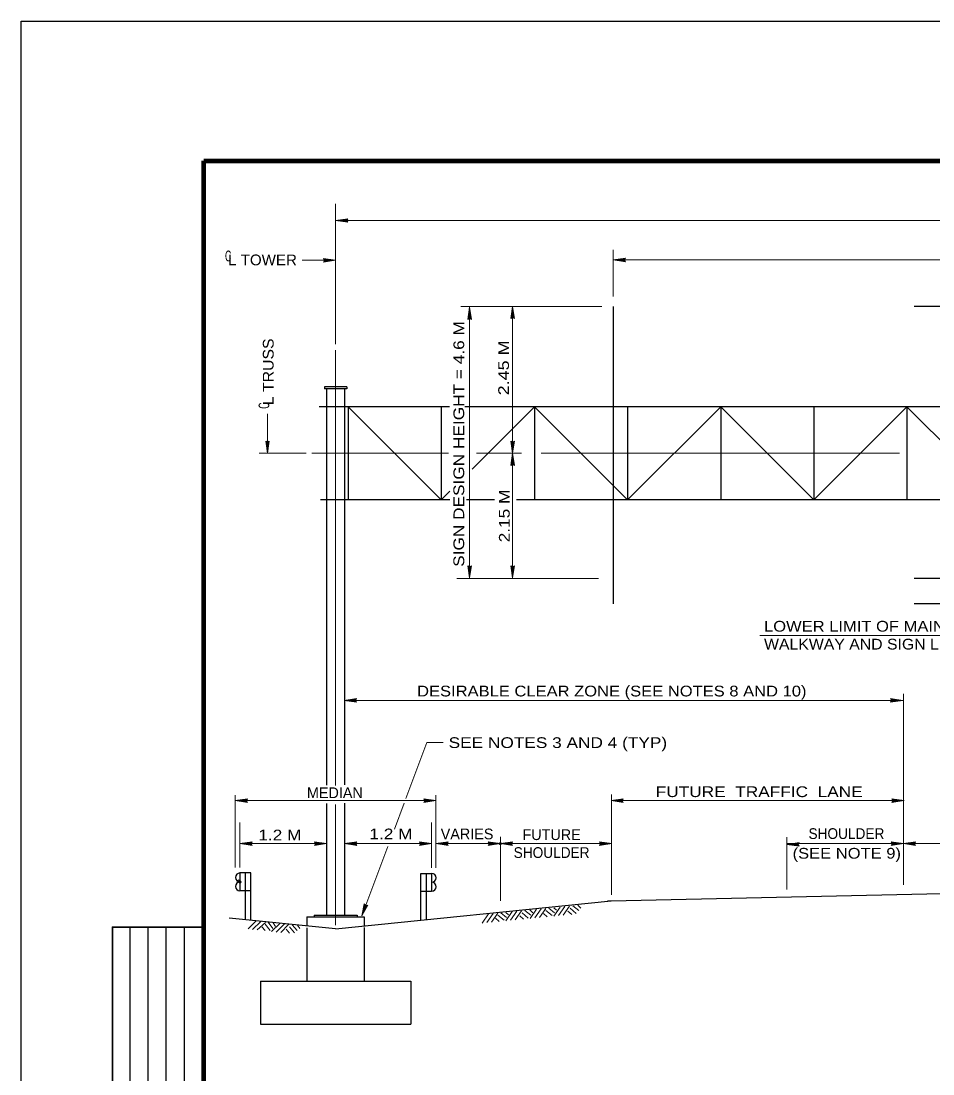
# Model space of a CAD drawing. Extents: x 312601.858 to 312602.699, y 144420.127 to 144420.721.
# Drawn here: x 312601.8578 to 312602.1123, y 144420.4268 to 144420.7208 of the extents above; entities that cross this region are included whole.
import ezdxf
from ezdxf.enums import TextEntityAlignment as Align

# ---------------------------------------------------------------- set-up
doc = ezdxf.new("R2010")
doc.units = 0
doc.header["$LTSCALE"] = 0.0012
doc.header["$PDMODE"] = 32
doc.header["$PDSIZE"] = 0.0006
doc.linetypes.add('DOT_DASHED', pattern=[7.7, 5, -1.2, 0.3, -1.2])
doc.linetypes.add('LONG_DASHED', pattern=[7.5, 6, -1.5])
for name, color, linetype, lineweight in [('1', 7, 'Continuous', 13), ('2', 7, 'Continuous', 13), ('39', 7, 'Continuous', 13), ('60', 7, 'Continuous', 25)]:
    doc.layers.add(name, color=color, linetype=linetype, lineweight=lineweight)

msp = doc.modelspace()

# ---------------------------------------------------------------- hatches: boundary and pattern name
at = {"layer": '39'}
for points in [[(312601.9487, 144420.6651), (312601.949, 144420.6646), (312601.9456, 144420.6651), (312601.949, 144420.6656)], [(312601.9425, 144420.654), (312601.9422, 144420.6545), (312601.9456, 144420.654), (312601.9422, 144420.6535)], [(312601.9425, 144420.654), (312601.9422, 144420.6545), (312601.9456, 144420.654), (312601.9422, 144420.6535)], [(312602.0262, 144420.6541), (312602.0265, 144420.6536), (312602.0231, 144420.6541), (312602.0265, 144420.6546)], [(312601.983, 144420.6378), (312601.9825, 144420.6375), (312601.983, 144420.6409), (312601.9835, 144420.6375)], [(312601.983, 144420.6378), (312601.9825, 144420.6375), (312601.983, 144420.6409), (312601.9835, 144420.6375)], [(312601.995, 144420.638), (312601.9945, 144420.6377), (312601.995, 144420.6411), (312601.9955, 144420.6377)], [(312601.995, 144420.638), (312601.9945, 144420.6377), (312601.995, 144420.6411), (312601.9955, 144420.6377)], [(312601.9266, 144420.6032), (312601.9271, 144420.6035), (312601.9266, 144420.6001), (312601.9261, 144420.6035)], [(312601.995, 144420.6032), (312601.9955, 144420.6035), (312601.995, 144420.6001), (312601.9945, 144420.6035)], [(312601.995, 144420.6032), (312601.9955, 144420.6035), (312601.995, 144420.6001), (312601.9945, 144420.6035)], [(312601.995, 144420.597), (312601.9945, 144420.5967), (312601.995, 144420.6001), (312601.9955, 144420.5967)], [(312601.995, 144420.597), (312601.9945, 144420.5967), (312601.995, 144420.6001), (312601.9955, 144420.5967)], [(312601.983, 144420.5684), (312601.9835, 144420.5687), (312601.983, 144420.5653), (312601.9825, 144420.5687)], [(312601.983, 144420.5684), (312601.9835, 144420.5687), (312601.983, 144420.5653), (312601.9825, 144420.5687)], [(312601.995, 144420.5684), (312601.9955, 144420.5687), (312601.995, 144420.5653), (312601.9945, 144420.5687)], [(312601.995, 144420.5684), (312601.9955, 144420.5687), (312601.995, 144420.5653), (312601.9945, 144420.5687)], [(312601.9511, 144420.5311), (312601.9514, 144420.5306), (312601.948, 144420.5311), (312601.9514, 144420.5316)], [(312602.1008, 144420.5311), (312602.1005, 144420.5316), (312602.1039, 144420.5311), (312602.1005, 144420.5306)], [(312602.1008, 144420.5311), (312602.1005, 144420.5316), (312602.1039, 144420.5311), (312602.1005, 144420.5306)], [(312601.9207, 144420.5031), (312601.921, 144420.5026), (312601.9176, 144420.5031), (312601.921, 144420.5036)], [(312601.9705, 144420.5031), (312601.9702, 144420.5036), (312601.9736, 144420.5031), (312601.9702, 144420.5026)], [(312602.0256, 144420.5031), (312602.0259, 144420.5026), (312602.0225, 144420.5031), (312602.0259, 144420.5036)], [(312602.1012, 144420.5031), (312602.1009, 144420.5036), (312602.1043, 144420.5031), (312602.1009, 144420.5026)], [(312601.922, 144420.4911), (312601.9223, 144420.4906), (312601.9189, 144420.4911), (312601.9223, 144420.4916)], [(312601.94, 144420.4911), (312601.9397, 144420.4916), (312601.9431, 144420.4911), (312601.9397, 144420.4906)], [(312601.94, 144420.4911), (312601.9397, 144420.4916), (312601.9431, 144420.4911), (312601.9397, 144420.4906)], [(312601.9512, 144420.4911), (312601.9515, 144420.4906), (312601.9481, 144420.4911), (312601.9515, 144420.4916)], [(312601.9693, 144420.4911), (312601.969, 144420.4916), (312601.9724, 144420.4911), (312601.969, 144420.4906)], [(312601.9767, 144420.4911), (312601.977, 144420.4906), (312601.9736, 144420.4911), (312601.977, 144420.4916)], [(312601.9885, 144420.4911), (312601.9882, 144420.4916), (312601.9916, 144420.4911), (312601.9882, 144420.4906)], [(312601.9947, 144420.4911), (312601.995, 144420.4906), (312601.9916, 144420.4911), (312601.995, 144420.4916)], [(312602.0196, 144420.4911), (312602.0193, 144420.4916), (312602.0227, 144420.4911), (312602.0193, 144420.4906)], [(312602.101, 144420.4911), (312602.1007, 144420.4916), (312602.1041, 144420.4911), (312602.1007, 144420.4906)], [(312602.101, 144420.4911), (312602.1007, 144420.4916), (312602.1041, 144420.4911), (312602.1007, 144420.4906)], [(312602.1072, 144420.4911), (312602.1075, 144420.4906), (312602.1041, 144420.4911), (312602.1075, 144420.4916)], [(312602.1072, 144420.4911), (312602.1075, 144420.4906), (312602.1041, 144420.4911), (312602.1075, 144420.4916)], [(312602.0747, 144420.4909), (312602.075, 144420.4904), (312602.0716, 144420.4909), (312602.075, 144420.4914)], [(312601.954, 144420.4738), (312601.9546, 144420.4739), (312601.9529, 144420.4709), (312601.9536, 144420.4743)]]:
    msp.add_hatch(color=256, dxfattribs=at).paths.add_polyline_path(points)

# ---------------------------------------------------------------- linework, layer by layer
at = {"layer": '1'}
for p, q in [((312602.0132, 144420.4739), (312602.0141, 144420.4731)), ((312601.9865, 144420.4689), (312601.9883, 144420.4715)), ((312601.9878, 144420.4691), (312601.9896, 144420.4716)), ((312601.9891, 144420.4692), (312601.9909, 144420.4717)), ((312601.9909, 144420.4711), (312601.9927, 144420.4697)), ((312601.9917, 144420.4718), (312601.9933, 144420.4705)), ((312601.9931, 144420.4695), (312601.9949, 144420.4721)), ((312601.9931, 144420.4719), (312601.9939, 144420.4712)), ((312601.9944, 144420.4697), (312601.9962, 144420.4722)), ((312601.9957, 144420.4698), (312601.9975, 144420.4723)), ((312601.9977, 144420.4718), (312601.9994, 144420.4703)), ((312601.9984, 144420.4724), (312602.0001, 144420.4711)), ((312601.9998, 144420.4726), (312602.0007, 144420.4718)), ((312601.9999, 144420.4702), (312602.0017, 144420.4728)), ((312602.0012, 144420.4704), (312602.003, 144420.4729)), ((312602.0025, 144420.4705), (312602.0043, 144420.473)), ((312602.0036, 144420.4716), (312602.0047, 144420.4707)), ((312602.0043, 144420.4724), (312602.0061, 144420.471)), ((312602.0051, 144420.4731), (312602.0067, 144420.4718)), ((312602.0065, 144420.4708), (312602.0083, 144420.4734)), ((312602.0065, 144420.4732), (312602.0073, 144420.4725)), ((312602.0078, 144420.471), (312602.0096, 144420.4735)), ((312602.0091, 144420.4711), (312602.0109, 144420.4736)), ((312602.0104, 144420.4722), (312602.0115, 144420.4713)), ((312602.0111, 144420.4731), (312602.0128, 144420.4716)), ((312602.0118, 144420.4737), (312602.0135, 144420.4724)), ((312601.9212, 144420.4673), (312601.9234, 144420.4695)), ((312601.9224, 144420.4671), (312601.9247, 144420.4694)), ((312601.9237, 144420.467), (312601.926, 144420.4691)), ((312601.9259, 144420.4686), (312601.9273, 144420.4668)), ((312601.9268, 144420.4692), (312601.9281, 144420.4674)), ((312601.9277, 144420.4666), (312601.93, 144420.4688)), ((312601.9282, 144420.469), (312601.9288, 144420.468)), ((312601.929, 144420.4664), (312601.9313, 144420.4687)), ((312601.9303, 144420.4663), (312601.9325, 144420.4685)), ((312601.9335, 144420.4684), (312601.9349, 144420.4668)), ((312601.935, 144420.4683), (312601.9356, 144420.4674)), ((312601.9902, 144420.4703), (312601.9913, 144420.4694)), ((312601.997, 144420.4709), (312601.9981, 144420.47)), ((312601.925, 144420.4679), (312601.9259, 144420.4668)), ((312601.9318, 144420.4672), (312601.9327, 144420.4661)), ((312601.9327, 144420.4679), (312601.9341, 144420.4662))]:
    msp.add_line(p, q, dxfattribs=at)
at = {"layer": '2'}
for p, q in [((312601.9363, 144420.654), (312601.9456, 144420.654)), ((312601.9266, 144420.6001), (312601.9266, 144420.6111)), ((312602.064, 144420.5492), (312602.14, 144420.5492))]:
    msp.add_line(p, q, dxfattribs=at)
at = {"layer": '39', "lineweight": 25}
for p, q in [((312601.8578, 144420.1268), (312601.8578, 144420.7208)), ((312601.8578, 144420.7208), (312602.6988, 144420.7208)), ((312601.9487, 144420.6187), (312601.9425, 144420.6187)), ((312601.9425, 144420.6187), (312601.9425, 144420.6181)), ((312601.9487, 144420.6181), (312601.9425, 144420.6181)), ((312601.9431, 144420.6181), (312601.9431, 144420.5074)), ((312601.9481, 144420.6181), (312601.9481, 144420.5075)), ((312601.9487, 144420.6187), (312601.9487, 144420.6181)), ((312601.9774, 144420.6131), (312601.941, 144420.6131)), ((312601.9491, 144420.6131), (312601.9491, 144420.5871)), ((312601.9751, 144420.5871), (312601.9491, 144420.6131)), ((312601.9751, 144420.6131), (312601.9751, 144420.5871)), ((312602.4758, 144420.6131), (312601.9817, 144420.6131)), ((312601.9837, 144420.5957), (312602.0011, 144420.6131)), ((312602.0011, 144420.6131), (312602.0011, 144420.5871)), ((312602.0271, 144420.5871), (312602.0011, 144420.6131)), ((312602.0271, 144420.6131), (312602.0271, 144420.5871)), ((312602.0271, 144420.5871), (312602.0531, 144420.6131)), ((312602.0531, 144420.6131), (312602.0531, 144420.5871)), ((312602.0791, 144420.5871), (312602.0531, 144420.6131)), ((312602.0791, 144420.6131), (312602.0791, 144420.5871)), ((312602.0791, 144420.5871), (312602.1051, 144420.6131)), ((312602.1051, 144420.6131), (312602.1051, 144420.5871)), ((312602.1311, 144420.5871), (312602.1051, 144420.6131)), ((312601.9751, 144420.5871), (312601.9775, 144420.5895)), ((312601.9775, 144420.5871), (312601.9414, 144420.5871)), ((312601.99, 144420.5871), (312601.9821, 144420.5871)), ((312602.4764, 144420.5871), (312601.9961, 144420.5871)), ((312601.9431, 144420.5023), (312601.9431, 144420.4752)), ((312601.9481, 144420.5024), (312601.9481, 144420.4755)), ((312601.9204, 144420.4829), (312601.9204, 144420.4699)), ((312601.9694, 144420.4698), (312601.9694, 144420.4828)), ((312601.9709, 144420.4828), (312601.9709, 144420.4699)), ((312601.9219, 144420.4779), (312601.9189, 144420.4779)), ((312601.9694, 144420.4778), (312601.9724, 144420.4778)), ((312601.9694, 144420.4778), (312601.9724, 144420.4778)), ((312602.0225, 144420.4751), (312602.2078, 144420.4793)), ((312601.9431, 144420.4752), (312601.9431, 144420.4711)), ((312601.9456, 144420.4673), (312602.0225, 144420.4751)), ((312601.9481, 144420.4755), (312601.9481, 144420.4711)), ((312601.9396, 144420.4711), (312601.9516, 144420.4711)), ((312601.9396, 144420.4711), (312601.9396, 144420.4707)), ((312601.9431, 144420.4711), (312601.9516, 144420.4711)), ((312601.9516, 144420.4711), (312601.9516, 144420.4707)), ((312601.9456, 144420.4673), (312601.9159, 144420.4703)), ((312601.9376, 144420.4707), (312601.9536, 144420.4707)), ((312601.9376, 144420.4707), (312601.9376, 144420.4681)), ((312601.9536, 144420.4707), (312601.9536, 144420.4681))]:
    msp.add_line(p, q, dxfattribs=at)
at = {"layer": '39', "lineweight": 158}
for p, q in [((312601.9088, 144420.142), (312601.9088, 144420.6818)), ((312601.9088, 144420.6818), (312602.6838, 144420.6818))]:
    msp.add_line(p, q, dxfattribs=at)
at = {"layer": '39'}
for p, q in [((312601.9456, 144420.6698), (312601.9456, 144420.6306)), ((312602.4726, 144420.6651), (312601.9456, 144420.6651)), ((312602.0231, 144420.6569), (312602.0231, 144420.6439)), ((312602.4071, 144420.6541), (312602.0231, 144420.6541)), ((312602.0199, 144420.6411), (312601.9806, 144420.6411)), ((312601.983, 144420.5653), (312601.983, 144420.6409)), ((312602.0271, 144420.5871), (312602.0011, 144420.6131)), ((312602.0271, 144420.5871), (312602.0011, 144420.6131)), ((312602.0271, 144420.5871), (312602.0011, 144420.6131)), ((312602.0271, 144420.5871), (312602.0531, 144420.6131)), ((312602.0271, 144420.5871), (312602.0531, 144420.6131)), ((312602.0791, 144420.5871), (312602.1051, 144420.6131)), ((312602.0791, 144420.5871), (312602.1051, 144420.6131)), ((312601.9243, 144420.6001), (312601.9374, 144420.6001)), ((312601.9849, 144420.6001), (312601.9975, 144420.6001)), ((312602.019, 144420.5651), (312601.9794, 144420.5651)), ((312602.1041, 144420.5329), (312602.1041, 144420.4796)), ((312601.9481, 144420.5311), (312602.1039, 144420.5311)), ((312601.9711, 144420.5193), (312601.9652, 144420.5037)), ((312601.9756, 144420.5193), (312601.9711, 144420.5193)), ((312601.9176, 144420.5046), (312601.9176, 144420.4844)), ((312601.9736, 144420.5046), (312601.9736, 144420.4843)), ((312602.0226, 144420.5048), (312602.0226, 144420.4768)), ((312601.9176, 144420.5031), (312601.9736, 144420.5031)), ((312601.9647, 144420.5024), (312601.962, 144420.4951)), ((312602.0226, 144420.5031), (312602.1039, 144420.5031)), ((312601.9189, 144420.497), (312601.9189, 144420.4844)), ((312601.9724, 144420.497), (312601.9724, 144420.4843)), ((312601.9916, 144420.493), (312601.9916, 144420.4751)), ((312602.0716, 144420.4929), (312602.0716, 144420.4783)), ((312601.9205, 144420.4911), (312601.9431, 144420.4911)), ((312601.9481, 144420.4911), (312601.9724, 144420.4911)), ((312601.9602, 144420.4903), (312601.9529, 144420.4709)), ((312601.9736, 144420.4911), (312601.9904, 144420.4911)), ((312601.9916, 144420.4911), (312602.0225, 144420.4911)), ((312601.9709, 144420.4828), (312601.9709, 144420.4698)), ((312601.9456, 144420.4803), (312601.9456, 144420.4683)), ((312602.0215, 144420.4751), (312602.025, 144420.4751))]:
    msp.add_line(p, q, dxfattribs=at)
at = {"layer": '39', "linetype": 'LONG_DASHED', "lineweight": 25}
for p, q in [((312602.4071, 144420.6411), (312602.0231, 144420.6411)), ((312602.0231, 144420.6411), (312602.0231, 144420.5581)), ((312602.4071, 144420.5651), (312602.0231, 144420.5651)), ((312602.4071, 144420.5581), (312602.0231, 144420.5581)), ((312601.9376, 144420.4676), (312601.9376, 144420.4527)), ((312601.9536, 144420.4677), (312601.9536, 144420.4527)), ((312601.9246, 144420.4527), (312601.9246, 144420.4407)), ((312601.9246, 144420.4527), (312601.9666, 144420.4527)), ((312601.9666, 144420.4527), (312601.9666, 144420.4407)), ((312601.9246, 144420.4407), (312601.9666, 144420.4407))]:
    msp.add_line(p, q, dxfattribs=at)
at = {"layer": '39', "linetype": 'DOT_DASHED'}
for p, q in [((312601.9456, 144420.6289), (312601.9456, 144420.5542)), ((312601.939, 144420.6001), (312601.9771, 144420.6001)), ((312602.003, 144420.6001), (312602.4887, 144420.6001)), ((312601.9456, 144420.5543), (312601.9456, 144420.5073)), ((312601.9456, 144420.502), (312601.9456, 144420.4803))]:
    msp.add_line(p, q, dxfattribs=at)
at = {"layer": '39'}
for points in [[(312601.9487, 144420.6651), (312601.949, 144420.6646), (312601.9456, 144420.6651), (312601.949, 144420.6656)], [(312601.9425, 144420.654), (312601.9422, 144420.6545), (312601.9456, 144420.654), (312601.9422, 144420.6535)], [(312601.9425, 144420.654), (312601.9422, 144420.6545), (312601.9456, 144420.654), (312601.9422, 144420.6535)], [(312602.0262, 144420.6541), (312602.0265, 144420.6536), (312602.0231, 144420.6541), (312602.0265, 144420.6546)], [(312601.983, 144420.6378), (312601.9825, 144420.6375), (312601.983, 144420.6409), (312601.9835, 144420.6375)], [(312601.983, 144420.6378), (312601.9825, 144420.6375), (312601.983, 144420.6409), (312601.9835, 144420.6375)], [(312601.995, 144420.638), (312601.9945, 144420.6377), (312601.995, 144420.6411), (312601.9955, 144420.6377)], [(312601.995, 144420.638), (312601.9945, 144420.6377), (312601.995, 144420.6411), (312601.9955, 144420.6377)], [(312601.9266, 144420.6032), (312601.9271, 144420.6035), (312601.9266, 144420.6001), (312601.9261, 144420.6035)], [(312601.995, 144420.6032), (312601.9955, 144420.6035), (312601.995, 144420.6001), (312601.9945, 144420.6035)], [(312601.995, 144420.6032), (312601.9955, 144420.6035), (312601.995, 144420.6001), (312601.9945, 144420.6035)], [(312601.995, 144420.597), (312601.9945, 144420.5967), (312601.995, 144420.6001), (312601.9955, 144420.5967)], [(312601.995, 144420.597), (312601.9945, 144420.5967), (312601.995, 144420.6001), (312601.9955, 144420.5967)], [(312601.983, 144420.5684), (312601.9835, 144420.5687), (312601.983, 144420.5653), (312601.9825, 144420.5687)], [(312601.983, 144420.5684), (312601.9835, 144420.5687), (312601.983, 144420.5653), (312601.9825, 144420.5687)], [(312601.995, 144420.5684), (312601.9955, 144420.5687), (312601.995, 144420.5653), (312601.9945, 144420.5687)], [(312601.995, 144420.5684), (312601.9955, 144420.5687), (312601.995, 144420.5653), (312601.9945, 144420.5687)], [(312601.9511, 144420.5311), (312601.9514, 144420.5306), (312601.948, 144420.5311), (312601.9514, 144420.5316)], [(312602.1008, 144420.5311), (312602.1005, 144420.5316), (312602.1039, 144420.5311), (312602.1005, 144420.5306)], [(312602.1008, 144420.5311), (312602.1005, 144420.5316), (312602.1039, 144420.5311), (312602.1005, 144420.5306)], [(312601.9207, 144420.5031), (312601.921, 144420.5026), (312601.9176, 144420.5031), (312601.921, 144420.5036)], [(312601.9705, 144420.5031), (312601.9702, 144420.5036), (312601.9736, 144420.5031), (312601.9702, 144420.5026)], [(312602.0256, 144420.5031), (312602.0259, 144420.5026), (312602.0225, 144420.5031), (312602.0259, 144420.5036)], [(312602.1012, 144420.5031), (312602.1009, 144420.5036), (312602.1043, 144420.5031), (312602.1009, 144420.5026)], [(312601.922, 144420.4911), (312601.9223, 144420.4906), (312601.9189, 144420.4911), (312601.9223, 144420.4916)], [(312601.94, 144420.4911), (312601.9397, 144420.4916), (312601.9431, 144420.4911), (312601.9397, 144420.4906)], [(312601.94, 144420.4911), (312601.9397, 144420.4916), (312601.9431, 144420.4911), (312601.9397, 144420.4906)], [(312601.9512, 144420.4911), (312601.9515, 144420.4906), (312601.9481, 144420.4911), (312601.9515, 144420.4916)], [(312601.9693, 144420.4911), (312601.969, 144420.4916), (312601.9724, 144420.4911), (312601.969, 144420.4906)], [(312601.9767, 144420.4911), (312601.977, 144420.4906), (312601.9736, 144420.4911), (312601.977, 144420.4916)], [(312601.9885, 144420.4911), (312601.9882, 144420.4916), (312601.9916, 144420.4911), (312601.9882, 144420.4906)], [(312601.9947, 144420.4911), (312601.995, 144420.4906), (312601.9916, 144420.4911), (312601.995, 144420.4916)], [(312602.0196, 144420.4911), (312602.0193, 144420.4916), (312602.0227, 144420.4911), (312602.0193, 144420.4906)], [(312602.101, 144420.4911), (312602.1007, 144420.4916), (312602.1041, 144420.4911), (312602.1007, 144420.4906)], [(312602.101, 144420.4911), (312602.1007, 144420.4916), (312602.1041, 144420.4911), (312602.1007, 144420.4906)], [(312602.1072, 144420.4911), (312602.1075, 144420.4906), (312602.1041, 144420.4911), (312602.1075, 144420.4916)], [(312602.1072, 144420.4911), (312602.1075, 144420.4906), (312602.1041, 144420.4911), (312602.1075, 144420.4916)], [(312602.0747, 144420.4909), (312602.075, 144420.4904), (312602.0716, 144420.4909), (312602.075, 144420.4914)], [(312601.954, 144420.4738), (312601.9546, 144420.4739), (312601.9529, 144420.4709), (312601.9536, 144420.4743)]]:
    msp.add_lwpolyline(points, close=True, dxfattribs=at)
for points in [[(312601.995, 144420.5653), (312601.995, 144420.6001), (312601.995, 144420.6411)], [(312602.0716, 144420.4911), (312602.1041, 144420.4911), (312602.1711, 144420.4911)], [(312601.9694, 144420.4828), (312601.9724, 144420.4828), (312601.9724, 144420.4778)]]:
    msp.add_lwpolyline(points, dxfattribs=at)
at = {"layer": '39', "lineweight": 25}
for points in [[(312601.9219, 144420.4698), (312601.9219, 144420.4829), (312601.9189, 144420.4829), (312601.9189, 144420.4779)], [(312601.9694, 144420.4828), (312601.9724, 144420.4828), (312601.9724, 144420.4778)]]:
    msp.add_lwpolyline(points, dxfattribs=at)
for centre, start, end in [((312601.9189, 144420.48165), 90, 270), ((312601.9724, 144420.48155), 270, 90), ((312601.9189, 144420.47915), 90, 270), ((312601.9724, 144420.47905), 270, 90)]:
    msp.add_arc(centre, 0.00125, start, end, dxfattribs=at)
at = {"layer": '39'}
for centre in [(312601.9724, 144420.48155), (312601.9724, 144420.47905)]:
    msp.add_arc(centre, 0.00125, 270, 90, dxfattribs=at)
for p in [(312601.9916, 144420.4911), (312601.9186, 144420.4807), (312601.9189, 144420.4804)]:
    msp.add_point(p, dxfattribs=at)
at = {"layer": '60'}
for p, q in [((312601.8883, 144420.3648), (312601.8883, 144420.4678)), ((312601.8933, 144420.3648), (312601.8933, 144420.4678)), ((312601.8983, 144420.3648), (312601.8983, 144420.4678)), ((312601.9034, 144420.3648), (312601.9034, 144420.4678))]:
    msp.add_line(p, q, dxfattribs=at)
at = {"layer": '60', "lineweight": 35}
msp.add_lwpolyline([(312601.9084, 144420.3648), (312601.8833, 144420.3648), (312601.8833, 144420.4678), (312601.9084, 144420.4678)], dxfattribs=at)

# ---------------------------------------------------------------- texts
at = {"layer": '2'}
for s, width, p in [('C', 0.6, (312601.9156, 144420.6537)), ('L TOWER', 1.05, (312601.9252, 144420.6526)), ('1.2 M', 1.2, (312601.93005, 144420.492)), ('1.2 M', 1.2, (312601.96105, 144420.4923)), ('(SEE NOTE 9)', 1.15, (312602.0883, 144420.4869))]:
    msp.add_text(s, height=0.003, dxfattribs=dict(at, width=width)).set_placement(p, align=Align.CENTER)
for s, width, p in [('SIGN DESIGN HEIGHT = 4.6 M', 1.2, (312601.9815, 144420.6027)), ('L TRUSS', 1.1, (312601.9283, 144420.62285)), ('2.45 M', 1.25, (312601.994, 144420.62395)), ('C', 0.6, (312601.9271, 144420.6134)), ('2.15 M', 1.2, (312601.9942, 144420.5826))]:
    msp.add_text(s, height=0.003, rotation=90, dxfattribs=dict(at, width=width)).set_placement(p, align=Align.CENTER)
for s, width, p in [('LOWER LIMIT OF MAINTENANCE', 1.15, (312602.0652, 144420.5503)), ('WALKWAY AND SIGN LIGHTING', 1.1, (312602.0652, 144420.5453))]:
    msp.add_text(s, height=0.003, dxfattribs=dict(at, width=width)).set_placement(p)
for s, p in [('MEDIAN', (312601.9454, 144420.5038)), ('VARIES', (312601.9823, 144420.4923))]:
    msp.add_text(s, height=0.003, dxfattribs=at).set_placement(p, align=Align.CENTER)
at = {"layer": '39'}
for s, width, p in [('DESIRABLE CLEAR ZONE (SEE NOTES 8 AND 10)', 1.15, (312602.0227, 144420.5322)), ('SEE NOTES 3 AND 4 (TYP)', 1.2, (312602.00765, 144420.5178)), ('FUTURE  TRAFFIC  LANE', 1.2, (312602.06385, 144420.5041)), ('SHOULDER', 0.95, (312602.0882, 144420.4924)), ('SHOULDER', 0.95, (312602.0059, 144420.4871))]:
    msp.add_text(s, height=0.003, dxfattribs=dict(at, width=width)).set_placement(p, align=Align.CENTER)
msp.add_text('FUTURE', height=0.003, dxfattribs=at).set_placement((312602.0059, 144420.4921), align=Align.CENTER)

doc.saveas('drawing.dxf')
